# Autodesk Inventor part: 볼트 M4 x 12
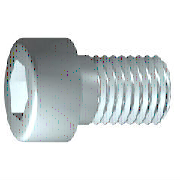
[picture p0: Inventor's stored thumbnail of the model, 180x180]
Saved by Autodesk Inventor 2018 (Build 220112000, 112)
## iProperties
IsCustomPart: 1
Created: 2012-02
Part Number: 볼트 M4 x 12
Material: 스테인리스강
Description: 6각 소켓 머리 캡 나사
Document SubType Name: Modeling
Standard: ISO 4762
Designer: mduedu
Standard Revision: Fourth edition 2004-03-01
Standards Organization: ISO
Language: ko-KR
Size Designation: M4 x 8
Categories: <MemberInstance><Categories><Category DisplayName="조임쇠" InternalName="e4da775c-781d-43d5-af7c-5136215cf5a6" Mnemonic="FSTN"><Category DisplayName="볼트" InternalN
Density: 7.75 g/cm^3
Appearance: 반광택
Author: mduedu
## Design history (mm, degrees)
sketch "스케치1"
  geometry: L1 (-1, 0)-(12, 0); L2 (12, 0)-(12, 2); L3 (12, 2)-(1.75, 2); L4 (1.75, 2)-(1.32, 2); L5 (1.32, 2)-(0, 2); L6 (0, 2)-(0, 3.5); L7 (0, 3.5)-(-4, 3.5); L8 (-4, 3.5)-(-4, 1.732); L9 (-4, 1.732)-(-2, 1.732); L10 (-2, 1.732)-(-1, 0); L11 (-7.2, 0)-(15.2, 0) reference; L12 (0, -0.7)-(0, 4.2) reference; L13 (1.75, 2)-(0, 2)
  constraints: 22 end point, 6 parallel, 2 collinear, 2 perpendicular, 1 horizontal, 1 point on line
  dimensions: "d1" = 10.25 distance from line of L3.end L2 (= GEL); "d2" = 0.42952 distance of L4.end L3.end (computed from GAL); "d3" = 4 distance between parallel lines of L8 L6 (= KOH); "d4" = 2 distance of L8.end L9.end (= INTI); "d5" = 60 deg angle of L10 L1; "d6" = 4 diameter of L3 L1 (= GD); "d7" = 4 diameter of L5 L1 (= BDM); "d8" = 3.4641 diameter of L9 L1 (= 1.1547 x SW); "d9" = 7 diameter of L7 L1 (= KOD); "d26" = 12 distance between parallel lines of L12 L2 (= NLG)
revolve "본체" sketch "스케치1" stored, may be unused: angle "d10" = 90 deg
sketch "스케치2"
  geometry: L1 (0, -4.9)-(0, 4.9) reference; L2 (-4.9, 0)-(4.9, 0) reference; L3 (1.732, 0)-(0.866, -1.5); L4 (0.866, -1.5)-(-0.866, -1.5); L5 (-0.866, -1.5)-(-1.732, 0); L6 (-1.732, 0)-(-0.866, 1.5); L7 (-0.866, 1.5)-(0.866, 1.5); L8 (0.866, 1.5)-(1.732, 0); 2 further points
  constraints: 12 end point, 1 coincident, 1 horizontal alignment, 1 point on line, 12 other
extrude "슬롯" join sketch "스케치2" stored distance "d11" = 10; taper "d12" = 0 deg
workplane "Work Plane1"
fillet "Fillet2" dims "d30" = 0.1 (= R)
body "Solid1"
fillet "모깎기1" dims "d17" = 0.4 (= RR)
feature "스레드" dims "d13" = 10.25 (= GEL), "d14" = 0
chamfer "모따기1" distance "d15" = 0.42941 (= -0.5 x SPD + 0.5 x GD); stored, may be unused: second distance "d16" = 0.42941 (= GUL), angle "d27" = 45 deg
other parameters: "GD" = 4 [user parameter; used in 2 equation terms], "NLG" = 12 [user parameter; used in 1 equation term], "GEL" = 10.25 [user parameter; used in 2 equation terms], "KOD" = 7 [user parameter; used in 1 equation term], "KOH" = 4 [user parameter; used in 1 equation term], "INTI" = 2 [user parameter; used in 1 equation term], "GAL" = 0.42941 (= 0.61345 x PTC) [user parameter; used in 1 equation term], "GUL" = 0.42941 (= 0.61345 x PTC) [user parameter; used in 1 equation term], "BDM" = 4 (= NND) [user parameter; used in 1 equation term], "SW" = 3 [user parameter; used in 2 equation terms], "RR" = 0.4 [user parameter; used in 1 equation term], "SPD" = 3.14117 (= NND - 1.2269 x PTC) [user parameter; used in 1 equation term], "d19" = 0, "d28" = 0, "d29" = 0, "R" = 0.1 [user parameter; used in 1 equation term], "TOA" = 30 deg [user parameter], "GD1" = 3.14117 (= THREADDIA - 1.2269 x PTC) [user parameter], "THREADDIA" = 4 [user parameter; used in 1 equation term], "FAWI" = 45 deg [user parameter], "TPU" = 14.28571 (computed from PTC) [user parameter], "PTC" = 0.7 [user parameter; used in 5 equation terms], "NND" = 4 [user parameter; used in 2 equation terms], "E0" = 3.465 (= 1.155 x SW) [user parameter]
